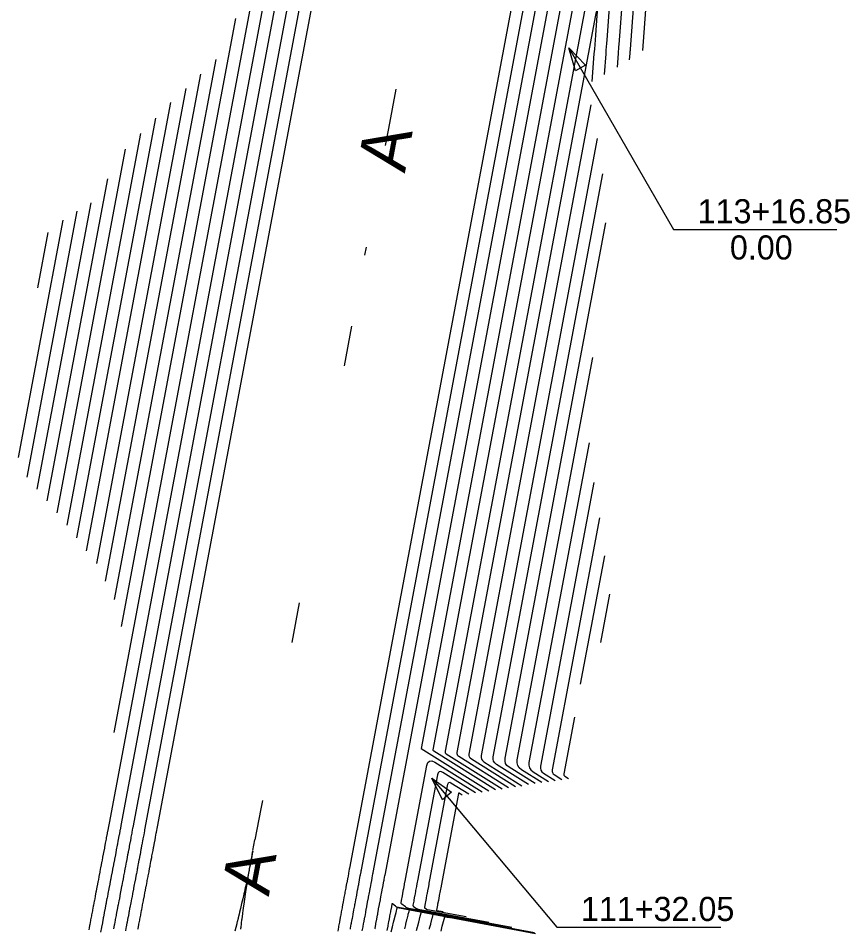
# Model space of a CAD drawing. Extents: x 688474 to 694748, y 765018 to 767373.
# Drawn here: x 688607.8 to 688814.5, y 766172.2 to 766398.7 of the extents above; entities that cross this region are included whole.
import ezdxf

# ---------------------------------------------------------------- set-up
doc = ezdxf.new("R2010")
doc.units = 0
for name, color, linetype in [('Prop_Contours_Major', 7, 'Continuous'), ('Prop_Contours_Minor', 7, 'Continuous'), ('R_Horz Alg', 7, 'Continuous'), ('R_Horz Alg Annot', 7, 'Continuous')]:
    doc.layers.add(name, color=color, linetype=linetype)

msp = doc.modelspace()

# ---------------------------------------------------------------- linework, layer by layer
at = {"layer": 'Prop_Contours_Major'}
for points in [[(688674.09, 766431.13), (688630.33, 766198.44), (688630.26, 766198.07), (688630.1, 766197.21), (688630.08, 766197.11), (688629.88, 766196.04), (688629.85, 766195.9), (688629.64, 766194.79), (688629.58, 766194.49), (688629.46, 766193.81), (688629.4, 766193.51), (688629.2, 766192.44), (688629.17, 766192.29), (688628.96, 766191.19), (688628.88, 766190.76), (688628.73, 766190), (688628.71, 766189.87), (688628.51, 766188.84), (688628.48, 766188.67), (688628.29, 766187.63), (688628.25, 766187.46), (688628.06, 766186.43), (688628.02, 766186.26), (688627.83, 766185.23), (688627.79, 766185.05), (688627.6, 766184.03), (688627.56, 766183.85), (688627.37, 766182.83), (688627.33, 766182.64), (688627.12, 766181.52), (688627.09, 766181.35), (688626.91, 766180.43), (688626.87, 766180.23), (688626.68, 766179.24), (688626.65, 766179.08), (688626.45, 766178.04), (688626.42, 766177.87), (688626.22, 766176.84), (688626.18, 766176.67), (688625.99, 766175.64), (688625.95, 766175.46), (688625.76, 766174.44), (688625.72, 766174.26), (688625.52, 766173.25), (688625.49, 766173.05), (688625.38, 766172.48), (688625.27, 766171.92)], [(688743.5, 766406.34), (688707.91, 766217.08), (688707.91, 766217.07), (688707.91, 766217.06), (688707.92, 766217.05), (688707.93, 766217.04), (688724.71, 766206.5)], [(688759.74, 766388.28), (688759.86, 766389.9), (688759.88, 766390.17), (688759.9, 766390.44), (688759.92, 766390.71), (688759.94, 766390.98), (688760.89, 766403.39)], [(688649.42, 766381.14), (688627.22, 766263.06)], [(688699.85, 766371.2), (688701.7, 766381.03)], [(688699.06, 766366.98), (688699.85, 766371.2)], [(688751.69, 766368.74), (688722.84, 766215.31), (688722.81, 766214.83), (688722.92, 766214.4), (688723.16, 766214.04), (688723.53, 766213.73), (688732.98, 766207.79)], [(688629.94, 766358.71), (688614.88, 766278.62)], [(688693.94, 766339.75), (688694.31, 766341.72)], [(688690.61, 766322.06), (688688.77, 766312.24)], [(688750.87, 766283.19), (688737.6, 766212.64), (688737.57, 766212.11), (688737.68, 766211.64), (688737.95, 766211.24), (688738.36, 766210.91), (688741.26, 766209.08)], [(688675.83, 766243.44), (688677.68, 766253.27)], [(688668.44, 766204.13), (688668.04, 766202.02)], [(688668.04, 766202.02), (688666.59, 766194.3)], [(688666.09, 766191.65), (688666.59, 766194.3)], [(688663.09, 766172.13), (688663.11, 766172.28), (688663.12, 766172.42), (688663.14, 766172.56), (688663.25, 766173.48), (688663.26, 766173.51), (688663.38, 766174.52), (688663.39, 766174.57), (688663.41, 766174.71), (688663.57, 766175.92), (688663.58, 766175.98), (688663.69, 766176.85), (688663.71, 766177), (688663.73, 766177.14), (688663.75, 766177.29), (688663.77, 766177.43), (688663.9, 766178.35), (688663.9, 766178.36), (688664.08, 766179.56), (688664.08, 766179.58), (688664.25, 766180.78), (688664.26, 766180.79), (688664.44, 766181.99), (688664.44, 766182.01), (688664.58, 766182.9), (688664.61, 766183.05), (688664.63, 766183.2), (688664.65, 766183.35), (688664.68, 766183.5), (688664.82, 766184.41), (688664.83, 766184.46), (688665.02, 766185.62), (688665.02, 766185.62), (688665.23, 766186.83), (688665.27, 766187.1), (688665.39, 766187.8), (688665.41, 766187.92), (688665.43, 766188.04), (688665.45, 766188.15), (688665.48, 766188.27), (688665.65, 766189.24), (688665.87, 766190.45), (688666.03, 766191.35), (688666.06, 766191.46), (688666.06, 766191.5), (688666.05, 766191.46), (688666.03, 766191.35), (688665.92, 766190.75), (688665.89, 766190.6), (688665.86, 766190.45), (688665.83, 766190.3), (688665.8, 766190.15), (688665.63, 766189.24), (688665.39, 766188.04), (688665.2, 766187.1), (688665.16, 766186.91), (688665.15, 766186.84), (688665.13, 766186.78), (688664.9, 766185.65), (688664.9, 766185.64), (688664.65, 766184.49), (688664.64, 766184.45), (688664.38, 766183.25), (688664.38, 766183.23), (688664.19, 766182.35), (688664.15, 766182.2), (688664.12, 766182.05), (688664.09, 766181.91), (688664.05, 766181.76), (688663.85, 766180.86), (688663.85, 766180.85), (688663.58, 766179.67), (688663.58, 766179.66), (688663.3, 766178.48), (688663.3, 766178.46), (688663.02, 766177.29), (688663.01, 766177.23), (688662.8, 766176.37), (688662.76, 766176.23), (688662.73, 766176.08), (688662.69, 766175.94), (688662.66, 766175.8), (688662.44, 766174.91), (688662.43, 766174.88), (688662.4, 766174.74), (688662.2, 766173.95), (688662.17, 766173.83), (688662.14, 766173.7), (688662.1, 766173.58), (688662.07, 766173.46), (688661.84, 766172.53), (688661.83, 766172.5), (688661.6, 766171.6)], [(688736.13, 766171.21), (688702.26, 766177.49), (688702.07, 766177.53), (688701.9, 766177.6), (688701.73, 766177.69), (688701.57, 766177.79), (688700.81, 766178.38), (688700.74, 766178.42), (688700.69, 766178.42), (688700.65, 766178.39), (688700.62, 766178.31), (688700.52, 766177.73), (688700.51, 766177.69), (688700.31, 766176.61), (688700.28, 766176.44), (688700.08, 766175.41), (688700.05, 766175.23), (688699.86, 766174.21), (688699.83, 766174.03), (688699.64, 766173.02), (688699.6, 766172.82), (688699.42, 766171.82)], [(688700.48, 766171.48), (688700.78, 766172.67), (688701.08, 766173.86), (688701.08, 766173.87), (688701.38, 766175.05), (688701.38, 766175.06), (688701.68, 766176.24), (688701.68, 766176.25), (688701.98, 766177.44), (688701.99, 766177.46), (688701.99, 766177.46), (688701.99, 766177.46), (688702, 766177.46), (688702, 766177.46), (688736.35, 766171)]]:
    msp.add_lwpolyline(points, dxfattribs=at)
at = {"layer": 'Prop_Contours_Minor'}
for points in [[(688671.08, 766431.37), (688631.52, 766220.99)], [(688676.97, 766430.25), (688633.28, 766197.9), (688633.25, 766197.75), (688633.08, 766196.84), (688633.04, 766196.62), (688633, 766196.39), (688632.83, 766195.49), (688632.8, 766195.34), (688632.62, 766194.39), (688632.59, 766194.21), (688632.55, 766194.04), (688632.4, 766193.25), (688632.35, 766192.96), (688632.14, 766191.88), (688632.12, 766191.73), (688631.91, 766190.63), (688631.9, 766190.59), (688631.69, 766189.48), (688631.66, 766189.32), (688631.46, 766188.27), (688631.43, 766188.12), (688631.23, 766187.07), (688631.2, 766186.92), (688631, 766185.87), (688630.97, 766185.72), (688630.8, 766184.81), (688630.76, 766184.59), (688630.72, 766184.36), (688630.54, 766183.46), (688630.51, 766183.31), (688630.31, 766182.26), (688630.28, 766182.11), (688630.07, 766180.98), (688630.04, 766180.82), (688629.85, 766179.85), (688629.82, 766179.7), (688629.65, 766178.8), (688629.61, 766178.58), (688629.56, 766178.35), (688629.39, 766177.45), (688629.36, 766177.3), (688629.16, 766176.24), (688629.13, 766176.1), (688628.96, 766175.19), (688628.91, 766174.97), (688628.87, 766174.74), (688628.69, 766173.84), (688628.67, 766173.69), (688628.46, 766172.64), (688628.43, 766172.49), (688628.21, 766171.36)], [(688679.9, 766429.59), (688636.24, 766197.43), (688636.2, 766197.19), (688636.01, 766196.2), (688635.97, 766196), (688635.79, 766195.02), (688635.76, 766194.86), (688635.73, 766194.7), (688635.55, 766193.77), (688635.51, 766193.55), (688635.36, 766192.72), (688635.3, 766192.42), (688635.1, 766191.38), (688635.07, 766191.19), (688634.95, 766190.59), (688634.85, 766190.04), (688634.65, 766188.98), (688634.61, 766188.78), (688634.43, 766187.81), (688634.39, 766187.64), (688634.36, 766187.48), (688634.19, 766186.58), (688634.15, 766186.37), (688633.96, 766185.37), (688633.92, 766185.17), (688633.73, 766184.17), (688633.69, 766183.96), (688633.5, 766182.97), (688633.46, 766182.76), (688633.28, 766181.79), (688633.25, 766181.63), (688633.22, 766181.47), (688633.01, 766180.42), (688632.98, 766180.25), (688632.81, 766179.34), (688632.77, 766179.16), (688632.58, 766178.16), (688632.54, 766177.95), (688632.35, 766176.98), (688632.32, 766176.82), (688632.29, 766176.66), (688632.12, 766175.75), (688632.08, 766175.55), (688631.89, 766174.55), (688631.85, 766174.34), (688631.66, 766173.35), (688631.61, 766173.14), (688631.43, 766172.17)], [(688682.91, 766429.33), (688639.18, 766196.82), (688639.14, 766196.6), (688638.94, 766195.54), (688638.89, 766195.26), (688638.76, 766194.56), (688638.73, 766194.43), (688638.71, 766194.31), (688638.69, 766194.18), (688638.66, 766194.06), (688638.49, 766193.12), (688638.44, 766192.91), (688638.3, 766192.16), (688638.25, 766191.89), (688638.03, 766190.72), (688637.98, 766190.45), (688637.81, 766189.53), (688637.75, 766189.24), (688637.58, 766188.32), (688637.52, 766188.04), (688637.39, 766187.34), (688637.37, 766187.21), (688637.34, 766187.09), (688637.32, 766186.96), (688637.29, 766186.84), (688637.12, 766185.91), (688637.1, 766185.83), (688636.89, 766184.71), (688636.87, 766184.63), (688636.66, 766183.51), (688636.61, 766183.23), (688636.43, 766182.3), (688636.38, 766182.02), (688636.24, 766181.32), (688636.22, 766181.2), (688636.2, 766181.07), (688636.17, 766180.95), (688636.15, 766180.82), (688635.96, 766179.86), (688635.93, 766179.68), (688635.74, 766178.69), (688635.73, 766178.62), (688635.51, 766177.49), (688635.45, 766177.21), (688635.32, 766176.51), (688635.27, 766176.26), (688635.22, 766176.02), (688635.05, 766175.09), (688635.03, 766175.01), (688634.81, 766173.89), (688634.76, 766173.6), (688634.58, 766172.68), (688634.53, 766172.4), (688634.39, 766171.7)], [(688637.53, 766172.1), (688637.56, 766172.27), (688637.73, 766173.17), (688637.77, 766173.37), (688637.96, 766174.38), (688638, 766174.57), (688638.2, 766175.58), (688638.23, 766175.77), (688638.43, 766176.78), (688638.46, 766176.98), (688638.66, 766178), (688638.69, 766178.17), (688638.89, 766179.17), (688638.92, 766179.33), (688639.12, 766180.39), (688639.16, 766180.58), (688639.34, 766181.55), (688639.37, 766181.72), (688639.41, 766181.9), (688639.58, 766182.8), (688639.62, 766182.99), (688639.81, 766184), (688639.84, 766184.19), (688640.04, 766185.2), (688640.07, 766185.39), (688640.27, 766186.41), (688640.3, 766186.6), (688640.49, 766187.56), (688640.52, 766187.74), (688640.55, 766187.91), (688640.75, 766188.94), (688640.76, 766188.99), (688640.94, 766189.97), (688640.98, 766190.14), (688641.01, 766190.31), (688641.2, 766191.35), (688641.26, 766191.65), (688641.41, 766192.45), (688641.45, 766192.65), (688641.62, 766193.58), (688641.66, 766193.75), (688641.69, 766193.93), (688641.86, 766194.83), (688641.9, 766195.02), (688642.08, 766195.98), (688642.13, 766196.25), (688642.37, 766197.53), (688685.77, 766428.35)], [(688731.82, 766409.14), (688690.1, 766187.32), (688690.05, 766187.05), (688689.87, 766186.06), (688689.83, 766185.87), (688689.65, 766184.91), (688689.62, 766184.73), (688689.59, 766184.56), (688689.42, 766183.65), (688689.38, 766183.47), (688689.22, 766182.59), (688689.16, 766182.3), (688688.97, 766181.29), (688688.94, 766181.12), (688688.91, 766180.95), (688688.73, 766179.96), (688688.72, 766179.91), (688688.53, 766178.89), (688688.49, 766178.72), (688688.46, 766178.54), (688688.29, 766177.64), (688688.26, 766177.45), (688688.07, 766176.43), (688688.03, 766176.24), (688687.85, 766175.28), (688687.82, 766175.1), (688687.79, 766174.93), (688687.62, 766174.03), (688687.59, 766173.84), (688687.4, 766172.82), (688687.36, 766172.63), (688687.18, 766171.62)], [(688690.32, 766172.12), (688690.37, 766172.4), (688690.54, 766173.32), (688690.59, 766173.6), (688690.72, 766174.3), (688690.75, 766174.42), (688690.77, 766174.55), (688690.79, 766174.67), (688690.82, 766174.8), (688690.99, 766175.73), (688691, 766175.8), (688691.21, 766176.93), (688691.26, 766177.21), (688691.4, 766177.91), (688691.42, 766178.04), (688691.44, 766178.16), (688691.46, 766178.29), (688691.49, 766178.41), (688691.67, 766179.37), (688691.68, 766179.42), (688691.89, 766180.54), (688691.9, 766180.62), (688692.12, 766181.78), (688692.17, 766182.07), (688692.34, 766182.95), (688692.39, 766183.23), (688692.52, 766183.93), (688692.54, 766184.05), (688692.57, 766184.18), (688692.59, 766184.3), (688692.61, 766184.43), (688692.79, 766185.36), (688692.84, 766185.63), (688692.97, 766186.34), (688693.02, 766186.59), (688693.07, 766186.84), (688734.7, 766408.22)], [(688693.29, 766171.66), (688693.47, 766172.65), (688693.51, 766172.86), (688693.69, 766173.83), (688693.72, 766173.99), (688693.75, 766174.16), (688693.92, 766175.06), (688693.96, 766175.27), (688694.14, 766176.26), (688694.18, 766176.47), (688694.36, 766177.44), (688694.39, 766177.61), (688694.42, 766177.77), (688694.62, 766178.82), (688694.62, 766178.86), (688694.81, 766179.88), (688694.85, 766180.08), (688695.06, 766181.2), (688695.12, 766181.52), (688695.27, 766182.29), (688695.3, 766182.48), (688695.48, 766183.46), (688695.51, 766183.62), (688695.55, 766183.79), (688695.71, 766184.69), (688695.75, 766184.9), (688695.94, 766185.87), (688695.98, 766186.11), (688696, 766186.19), (688737.68, 766407.87)], [(688696.43, 766172.16), (688696.46, 766172.31), (688696.65, 766173.37), (688696.68, 766173.52), (688696.88, 766174.57), (688696.9, 766174.72), (688697.07, 766175.62), (688697.11, 766175.85), (688697.16, 766176.07), (688697.32, 766176.98), (688697.35, 766177.13), (688697.56, 766178.26), (688697.57, 766178.3), (688697.77, 766179.38), (688697.8, 766179.54), (688698.01, 766180.64), (688698.06, 766180.94), (688698.23, 766181.84), (688698.25, 766181.93), (688698.45, 766182.99), (688698.48, 766183.15), (688698.65, 766184.05), (688698.69, 766184.27), (688698.73, 766184.5), (688698.91, 766185.44), (688698.93, 766185.55), (688740.67, 766407.52)], [(688726.36, 766206.76), (688711.05, 766216.38), (688710.97, 766216.45), (688710.91, 766216.53), (688710.89, 766216.62), (688710.9, 766216.73), (688746.5, 766406.06)], [(688749.5, 766405.78), (688713.88, 766216.37), (688713.87, 766216.17), (688713.91, 766216), (688714.01, 766215.85), (688714.17, 766215.72), (688728.02, 766207.02)], [(688753.49, 766384.7), (688753.88, 766389.83), (688753.94, 766390.69), (688754.01, 766391.54), (688754.07, 766392.4), (688754.14, 766393.26), (688755.02, 766404.85)], [(688757.96, 766404.12), (688757.04, 766392.12), (688757, 766391.55), (688756.95, 766390.99), (688756.91, 766390.43), (688756.87, 766389.86), (688756.62, 766386.49)], [(688763.85, 766402.97), (688762.91, 766390.61)], [(688729.67, 766207.28), (688717.29, 766215.06), (688717.06, 766215.24), (688716.92, 766215.47), (688716.85, 766215.73), (688716.87, 766216.02), (688751.35, 766399.38), (688751.53, 766400.27), (688751.64, 766400.55), (688751.66, 766400.25), (688751.61, 766399.35), (688751.23, 766394.4), (688751.15, 766393.25), (688751.06, 766392.1), (688750.97, 766390.95), (688750.88, 766389.8), (688750.37, 766382.91)], [(688633.43, 766247.4), (688661.86, 766398.6)], [(688656.89, 766388.36), (688631.64, 766254.12)], [(688629.45, 766258.67), (688653.16, 766384.75)], [(688624.76, 766266.24), (688645.73, 766377.71)], [(688731.33, 766207.54), (688720.41, 766214.39), (688720.11, 766214.64), (688719.92, 766214.94), (688719.83, 766215.28), (688719.85, 766215.66), (688750.21, 766377.09)], [(688622.31, 766269.42), (688641.95, 766373.84)], [(688638.16, 766369.95), (688619.85, 766272.6)], [(688634.38, 766366.1), (688617.38, 766275.68)], [(688734.64, 766208.05), (688726.65, 766213.07), (688726.2, 766213.44), (688725.92, 766213.87), (688725.79, 766214.38), (688725.83, 766214.95), (688753.09, 766359.96)], [(688625.77, 766352.78), (688612.38, 766281.56)], [(688622.32, 766350.63), (688609.88, 766284.5)], [(688618.86, 766348.47), (688607.76, 766289.43)], [(688736.29, 766208.31), (688729.77, 766212.41), (688729.25, 766212.83), (688728.92, 766213.34), (688728.77, 766213.93), (688728.81, 766214.6), (688753.86, 766347.79)], [(688612.63, 766331.6), (688615.23, 766345.4)], [(688737.95, 766208.57), (688732.89, 766211.75), (688732.3, 766212.23), (688731.92, 766212.81), (688731.75, 766213.48), (688731.8, 766214.24), (688750.62, 766314.31)], [(688749.67, 766293.05), (688734.72, 766213.57), (688734.68, 766212.86), (688734.83, 766212.24), (688735.18, 766211.71), (688735.73, 766211.26), (688739.6, 766208.83)], [(688752.26, 766274.37), (688740.48, 766211.71), (688740.46, 766211.35), (688740.53, 766211.05), (688740.71, 766210.78), (688740.98, 766210.56), (688742.91, 766209.34)], [(688747.55, 766233.06), (688753.54, 766264.92)], [(688752.55, 766243.42), (688754.8, 766255.41)], [(688746.01, 766224.87), (688743.36, 766210.78), (688743.35, 766210.6), (688743.38, 766210.45), (688743.47, 766210.32), (688743.61, 766210.2), (688744.57, 766209.6)], [(688730.45, 766172.53), (688704.82, 766177.28), (688704.6, 766177.33), (688704.39, 766177.41), (688704.19, 766177.52), (688704, 766177.65), (688703.08, 766178.35), (688703, 766178.43), (688702.95, 766178.52), (688702.93, 766178.62), (688702.94, 766178.74), (688703.11, 766179.68), (688703.17, 766179.98), (688703.34, 766180.88), (688703.35, 766180.96), (688703.56, 766182.05), (688703.58, 766182.17), (688703.79, 766183.25), (688703.81, 766183.38), (688704.02, 766184.48), (688704.04, 766184.58), (688709.34, 766212.78), (688709.59, 766213.53), (688710, 766213.92), (688710.57, 766213.96), (688711.29, 766213.63), (688723.05, 766206.25)], [(688721.39, 766205.99), (688713.31, 766211.07), (688712.81, 766211.29), (688712.42, 766211.27), (688712.14, 766211), (688711.96, 766210.48), (688707, 766184.1), (688706.95, 766183.82), (688706.77, 766182.9), (688706.73, 766182.69), (688706.55, 766181.69), (688706.51, 766181.49), (688706.31, 766180.46), (688706.28, 766180.3), (688706.12, 766179.41), (688706.06, 766179.11), (688705.87, 766178.11), (688705.86, 766178.03), (688705.88, 766177.96), (688705.91, 766177.9), (688705.97, 766177.84), (688706.6, 766177.36), (688706.73, 766177.27), (688706.87, 766177.2), (688707.01, 766177.14), (688707.17, 766177.1), (688724.76, 766173.84)], [(688719.08, 766175.16), (688709.51, 766176.93), (688709.43, 766176.95), (688709.35, 766176.98), (688709.27, 766177.02), (688709.2, 766177.07), (688708.86, 766177.34), (688708.83, 766177.37), (688708.81, 766177.4), (688708.8, 766177.44), (688708.8, 766177.48), (688709.02, 766178.59), (688709.07, 766178.9), (688709.23, 766179.71), (688709.26, 766179.89), (688709.45, 766180.91), (688709.49, 766181.09), (688709.68, 766182.12), (688709.71, 766182.29), (688709.89, 766183.21), (688709.94, 766183.51), (688710.11, 766184.39), (688714.58, 766208.19), (688714.68, 766208.47), (688714.83, 766208.62), (688715.05, 766208.63), (688715.32, 766208.51), (688719.74, 766205.73)], [(688718.08, 766205.47), (688717.33, 766205.95), (688717.28, 766205.97), (688717.25, 766205.97), (688717.22, 766205.94), (688717.2, 766205.89), (688712.88, 766182.89), (688712.87, 766182.82), (688712.65, 766181.65), (688712.64, 766181.63), (688712.42, 766180.45), (688712.42, 766180.43), (688712.19, 766179.24), (688712.01, 766178.29), (688711.96, 766178.04), (688711.74, 766176.85), (688711.74, 766176.84), (688711.74, 766176.84), (688711.74, 766176.83), (688711.75, 766176.83), (688711.8, 766176.78), (688711.81, 766176.78), (688711.83, 766176.77), (688711.84, 766176.77), (688711.85, 766176.76), (688713.4, 766176.48)], [(688731, 766172), (688704.95, 766176.9), (688704.94, 766176.9), (688704.94, 766176.9), (688704.94, 766176.9), (688704.94, 766176.89), (688704.82, 766176.45), (688704.64, 766175.72), (688704.61, 766175.6), (688704.35, 766174.57), (688704.31, 766174.41), (688704.05, 766173.38), (688704.01, 766173.22), (688703.75, 766172.19)], [(688725.66, 766172.99), (688707.89, 766176.34), (688707.89, 766176.34), (688707.89, 766176.34), (688707.88, 766176.33), (688707.88, 766176.33), (688707.88, 766176.31), (688707.61, 766175.27), (688707.58, 766175.13), (688707.54, 766174.98), (688707.31, 766174.08), (688707.28, 766173.94), (688707.24, 766173.79), (688707.01, 766172.89), (688706.98, 766172.75), (688706.94, 766172.6), (688706.71, 766171.7)], [(688720.31, 766173.99), (688710.83, 766175.77), (688710.83, 766175.77), (688710.83, 766175.77), (688710.55, 766174.65), (688710.51, 766174.49), (688710.24, 766173.46), (688710.21, 766173.31), (688709.94, 766172.27), (688709.9, 766172.12)], [(688712.87, 766171.64), (688713.17, 766172.83), (688713.48, 766174.02), (688713.78, 766175.21), (688714.97, 766174.98)]]:
    msp.add_lwpolyline(points, dxfattribs=at)
at = {"layer": 'R_Horz Alg'}
for p, q in [((688776.65, 766346.15), (688811.25, 766346.15)), ((688747.62, 766172.64), (688782.42, 766172.64))]:
    msp.add_line(p, q, dxfattribs=at)
for points in [[(688744.63, 766391.33), (688770.65, 766346.15), (688776.65, 766346.15)], [(688710.59, 766209.69), (688741.62, 766172.64), (688747.62, 766172.64)]]:
    msp.add_lwpolyline(points, dxfattribs=at)
for points in [[(688744.63, 766391.33), (688748.79, 766387.02), (688746.27, 766385.56)], [(688710.59, 766209.69), (688715.44, 766206.17), (688713.21, 766204.3)]]:
    msp.add_lwpolyline(points, close=True, dxfattribs=at)

# ---------------------------------------------------------------- texts
for p in [(688703.85, 766359.98), (688670.02, 766180.09)]:
    msp.add_text('A', height=12, rotation=79.35, dxfattribs=at).set_placement(p)
at = {"layer": 'R_Horz Alg Annot'}
for s, p in [('113+16.85', (688776.65, 766347.65)), ('0.00', (688784.66, 766338.65)), ('111+32.05', (688747.62, 766174.14))]:
    msp.add_text(s, height=6, dxfattribs=at).set_placement(p)

doc.saveas('drawing.dxf')
